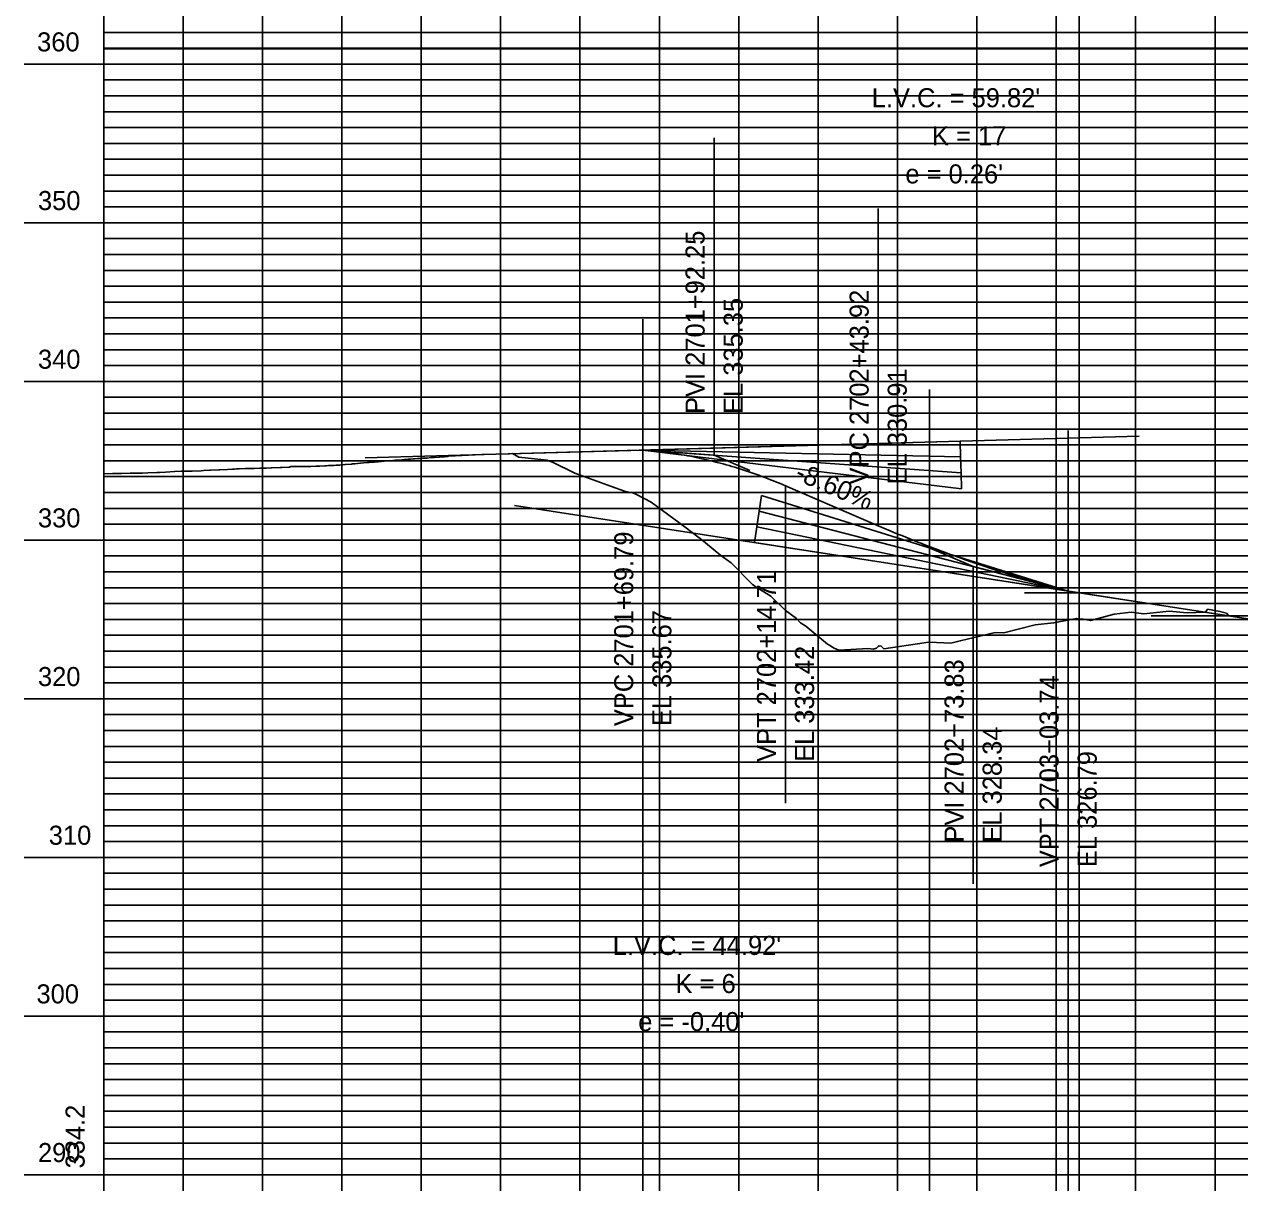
# Model space of a CAD drawing. Extents: x 1195880 to 1289360, y 2059330 to 2086925.
# Drawn here: x 1197038.8 to 1197421.6, y 2062321.8 to 2062686.8 of the extents above; entities that cross this region are included whole.
import ezdxf

# ---------------------------------------------------------------- set-up
doc = ezdxf.new("R2010")
doc.units = 0
for name, color, linetype in [('41', 7, 'Continuous'), ('Clip', 7, 'Continuous'), ('Default', 7, 'Continuous'), ('Existing Ground PGL', 7, 'Continuous'), ('Grid', 7, 'Continuous'), ('Grid Lables', 7, 'Continuous'), ('Profile', 7, 'Continuous'), ('Profile Annotation', 7, 'Continuous')]:
    doc.layers.add(name, color=color, linetype=linetype)

msp = doc.modelspace()

# ---------------------------------------------------------------- linework, layer by layer
at = {"layer": 'Clip'}
msp.add_lwpolyline([(1197063.84, 2062324.28), (1197483, 2062324.28), (1197483, 2062679.07), (1197063.84, 2062679.07)], close=True, dxfattribs=at)
at = {"layer": 'Default'}
for p, q in [((1197371.02, 2062224.28), (1197371.02, 2062868.37)), ((1197233.63, 2062274.28), (1197233.63, 2062593.89)), ((1197323.88, 2062224.28), (1197323.88, 2062571.74)), ((1197146.17, 2062550.17), (1197389.96, 2062557.06)), ((1197367.58, 2062274.28), (1197367.58, 2062558.8)), ((1197233.63, 2062552.64), (1197333.59, 2062555.47)), ((1197334.02, 2062540.47), (1197233.63, 2062552.64)), ((1197233.63, 2062552.64), (1197333.88, 2062545.47)), ((1197333.73, 2062550.47), (1197233.63, 2062552.64)), ((1197333.59, 2062555.47), (1197333.73, 2062550.47)), ((1197333.73, 2062550.47), (1197333.88, 2062545.47)), ((1197333.88, 2062545.47), (1197334.02, 2062540.47)), ((1197270.29, 2062533.39), (1197271.06, 2062538.34)), ((1197271.06, 2062538.34), (1197367.58, 2062508.21)), ((1197193.27, 2062535.2), (1197429.6, 2062498.61)), ((1197269.53, 2062528.45), (1197270.29, 2062533.39)), ((1197367.58, 2062508.21), (1197270.29, 2062533.39)), ((1197268.76, 2062523.51), (1197269.53, 2062528.45)), ((1197269.53, 2062528.45), (1197367.58, 2062508.21)), ((1197367.58, 2062508.21), (1197268.76, 2062523.51)), ((1197588.84, 2062507.68), (1197353.89, 2062507.68)), ((1197588.84, 2062500.38), (1197393.7, 2062500.38))]:
    msp.add_line(p, q, dxfattribs=at)
at = {"layer": 'Existing Ground PGL'}
msp.add_lwpolyline([(1197063.84, 2062545.18), (1197066.63, 2062545.22), (1197067.43, 2062545.24), (1197069.42, 2062545.28), (1197072.21, 2062545.33), (1197074.99, 2062545.39), (1197076.11, 2062545.42), (1197077.78, 2062545.48), (1197080.57, 2062545.59), (1197081.39, 2062545.62), (1197083.36, 2062545.73), (1197086.14, 2062545.9), (1197088.28, 2062546.05), (1197088.93, 2062546.03), (1197090.4, 2062545.99), (1197091.22, 2062545.97), (1197091.72, 2062546), (1197094.51, 2062546.13), (1197095.28, 2062546.17), (1197097.29, 2062546.27), (1197097.52, 2062546.28), (1197100.08, 2062546.41), (1197100.46, 2062546.43), (1197102.87, 2062546.56), (1197104.44, 2062546.65), (1197105.04, 2062546.68), (1197105.66, 2062546.72), (1197106.53, 2062546.77), (1197108.44, 2062546.82), (1197109.19, 2062546.84), (1197110.1, 2062546.86), (1197111.23, 2062546.89), (1197113.03, 2062546.93), (1197114.02, 2062546.96), (1197115.01, 2062546.98), (1197116.62, 2062547.02), (1197116.81, 2062547.03), (1197119.41, 2062547.12), (1197119.59, 2062547.13), (1197119.98, 2062547.14), (1197122.15, 2062547.23), (1197122.34, 2062547.29), (1197122.38, 2062547.3), (1197122.77, 2062547.42), (1197123.07, 2062547.52), (1197125.17, 2062547.51), (1197127.96, 2062547.5), (1197129.12, 2062547.49), (1197130.64, 2062547.57), (1197130.74, 2062547.57), (1197131.92, 2062547.62), (1197133.53, 2062547.7), (1197133.92, 2062547.72), (1197134.62, 2062547.74), (1197136.32, 2062547.84), (1197137.04, 2062547.88), (1197137.22, 2062547.89), (1197138.2, 2062547.94), (1197139.11, 2062548.02), (1197139.75, 2062548.07), (1197140.03, 2062548.1), (1197141.89, 2062548.26), (1197142.21, 2062548.29), (1197142.89, 2062548.35), (1197144.59, 2062548.49), (1197144.68, 2062548.5), (1197145.64, 2062548.58), (1197146.91, 2062548.69), (1197147.47, 2062548.74), (1197148.3, 2062548.81), (1197149.17, 2062548.89), (1197150.26, 2062548.99), (1197150.87, 2062549.05), (1197151.38, 2062549.1), (1197153.04, 2062549.22), (1197153.37, 2062549.24), (1197153.55, 2062549.25), (1197154.86, 2062549.36), (1197155.67, 2062549.42), (1197155.79, 2062549.43), (1197155.83, 2062549.43), (1197157.74, 2062549.59), (1197158.14, 2062549.62), (1197158.62, 2062549.66), (1197159.78, 2062549.75), (1197160.43, 2062549.79), (1197161.41, 2062549.87), (1197161.78, 2062549.9), (1197162.67, 2062549.96), (1197163.75, 2062550.03), (1197164.2, 2062550.06), (1197164.87, 2062550.1), (1197165.67, 2062550.15), (1197166.88, 2062550.26), (1197166.98, 2062550.27), (1197168.05, 2062550.35), (1197169.46, 2062550.45), (1197169.77, 2062550.47), (1197171.18, 2062550.57), (1197172.33, 2062550.66), (1197172.47, 2062550.68), (1197172.48, 2062550.68), (1197182.95, 2062551.21), (1197191.6, 2062551.45), (1197192.61, 2062551.57), (1197194.56, 2062550.38), (1197203.5, 2062549.42), (1197204.26, 2062549.17), (1197205.22, 2062548.81), (1197212.2, 2062545.38), (1197223.74, 2062541.13), (1197227.89, 2062539.74), (1197230.65, 2062539.05), (1197231.6, 2062538.69), (1197236.29, 2062536.19), (1197246.92, 2062528.33), (1197251.01, 2062525.35), (1197251.69, 2062524.75), (1197253.42, 2062523.45), (1197258.25, 2062519.43), (1197261.43, 2062517.16), (1197268.1, 2062510.38), (1197268.21, 2062510.3), (1197268.38, 2062510.16), (1197269.06, 2062509.63), (1197273.93, 2062506.58), (1197278.46, 2062502.15), (1197282, 2062499.59), (1197283.3, 2062498.21), (1197285.02, 2062497.11), (1197291.84, 2062491.52), (1197291.96, 2062491.41), (1197292.03, 2062491.35), (1197293.94, 2062490.25), (1197295.36, 2062489.6), (1197304.67, 2062490.08), (1197306.21, 2062489.96), (1197307.25, 2062490.23), (1197307.93, 2062491.01), (1197308.06, 2062490.81), (1197308.62, 2062490.97), (1197309.52, 2062490.06), (1197322.23, 2062491.86), (1197323.6, 2062492.07), (1197323.95, 2062492.12), (1197330.61, 2062491.81), (1197333.6, 2062492.51), (1197344.59, 2062495.13), (1197347.32, 2062495.01), (1197357.2, 2062497.55), (1197363.02, 2062498.2), (1197370.18, 2062499.59), (1197372.36, 2062499.39), (1197374.64, 2062498.95), (1197376.59, 2062499.48), (1197382.12, 2062500.92), (1197387.43, 2062501.53), (1197391.39, 2062501.07), (1197399.36, 2062501.86), (1197405.1, 2062501.36), (1197410.85, 2062501.52), (1197411.22, 2062502.24), (1197411.48, 2062502.51), (1197415.36, 2062501.8), (1197417.41, 2062501.26), (1197418.18, 2062500.4), (1197428.81, 2062498.76)], dxfattribs=at)
at = {"layer": 'Grid'}
for p, q in [((1197063.84, 2062224.28), (1197063.84, 2062824.28)), ((1197088.84, 2062224.28), (1197088.84, 2062824.28)), ((1197113.84, 2062224.28), (1197113.84, 2062824.28)), ((1197138.84, 2062224.28), (1197138.84, 2062824.28)), ((1197163.84, 2062224.28), (1197163.84, 2062824.28)), ((1197188.84, 2062224.28), (1197188.84, 2062824.28)), ((1197213.84, 2062224.28), (1197213.84, 2062824.28)), ((1197238.84, 2062224.28), (1197238.84, 2062824.28)), ((1197263.84, 2062224.28), (1197263.84, 2062824.28)), ((1197288.84, 2062224.28), (1197288.84, 2062824.28)), ((1197313.84, 2062224.28), (1197313.84, 2062824.28)), ((1197338.84, 2062224.28), (1197338.84, 2062824.28)), ((1197363.84, 2062224.28), (1197363.84, 2062824.28)), ((1197388.84, 2062224.28), (1197388.84, 2062824.28)), ((1197413.84, 2062224.28), (1197413.84, 2062824.28)), ((1197063.84, 2062684.28), (1197066.84, 2062684.28)), ((1197063.84, 2062684.28), (1197563.84, 2062684.28)), ((1197563.84, 2062684.28), (1197063.84, 2062684.28)), ((1197063.84, 2062679.28), (1197066.84, 2062679.28)), ((1197063.84, 2062679.28), (1197563.84, 2062679.28)), ((1197038.84, 2062674.28), (1197063.84, 2062674.28)), ((1197063.84, 2062674.28), (1197563.84, 2062674.28)), ((1197063.84, 2062669.28), (1197066.84, 2062669.28)), ((1197063.84, 2062669.28), (1197563.84, 2062669.28)), ((1197063.84, 2062664.28), (1197066.84, 2062664.28)), ((1197063.84, 2062664.28), (1197563.84, 2062664.28)), ((1197563.84, 2062664.28), (1197063.84, 2062664.28)), ((1197063.84, 2062659.28), (1197066.84, 2062659.28)), ((1197063.84, 2062659.28), (1197563.84, 2062659.28)), ((1197063.84, 2062654.28), (1197066.84, 2062654.28)), ((1197063.84, 2062654.28), (1197563.84, 2062654.28)), ((1197563.84, 2062654.28), (1197063.84, 2062654.28)), ((1197063.84, 2062649.28), (1197066.84, 2062649.28)), ((1197063.84, 2062649.28), (1197563.84, 2062649.28)), ((1197063.84, 2062644.28), (1197066.84, 2062644.28)), ((1197063.84, 2062644.28), (1197563.84, 2062644.28)), ((1197563.84, 2062644.28), (1197063.84, 2062644.28)), ((1197063.84, 2062639.28), (1197066.84, 2062639.28)), ((1197063.84, 2062639.28), (1197563.84, 2062639.28)), ((1197063.84, 2062634.28), (1197066.84, 2062634.28)), ((1197063.84, 2062634.28), (1197563.84, 2062634.28)), ((1197563.84, 2062634.28), (1197063.84, 2062634.28)), ((1197063.84, 2062629.28), (1197066.84, 2062629.28)), ((1197063.84, 2062629.28), (1197563.84, 2062629.28)), ((1197038.84, 2062624.28), (1197063.84, 2062624.28)), ((1197063.84, 2062624.28), (1197563.84, 2062624.28)), ((1197063.84, 2062619.28), (1197066.84, 2062619.28)), ((1197063.84, 2062619.28), (1197563.84, 2062619.28)), ((1197063.84, 2062614.28), (1197066.84, 2062614.28)), ((1197063.84, 2062614.28), (1197563.84, 2062614.28)), ((1197563.84, 2062614.28), (1197063.84, 2062614.28)), ((1197063.84, 2062609.28), (1197066.84, 2062609.28)), ((1197063.84, 2062609.28), (1197563.84, 2062609.28)), ((1197063.84, 2062604.28), (1197066.84, 2062604.28)), ((1197063.84, 2062604.28), (1197563.84, 2062604.28)), ((1197563.84, 2062604.28), (1197063.84, 2062604.28)), ((1197063.84, 2062599.28), (1197066.84, 2062599.28)), ((1197063.84, 2062599.28), (1197563.84, 2062599.28)), ((1197063.84, 2062594.28), (1197066.84, 2062594.28)), ((1197063.84, 2062594.28), (1197563.84, 2062594.28)), ((1197563.84, 2062594.28), (1197063.84, 2062594.28)), ((1197063.84, 2062589.28), (1197066.84, 2062589.28)), ((1197063.84, 2062589.28), (1197563.84, 2062589.28)), ((1197063.84, 2062584.28), (1197066.84, 2062584.28)), ((1197063.84, 2062584.28), (1197563.84, 2062584.28)), ((1197563.84, 2062584.28), (1197063.84, 2062584.28)), ((1197063.84, 2062579.28), (1197066.84, 2062579.28)), ((1197063.84, 2062579.28), (1197563.84, 2062579.28)), ((1197038.84, 2062574.28), (1197063.84, 2062574.28)), ((1197063.84, 2062574.28), (1197563.84, 2062574.28)), ((1197063.84, 2062569.28), (1197066.84, 2062569.28)), ((1197063.84, 2062569.28), (1197563.84, 2062569.28)), ((1197063.84, 2062564.28), (1197066.84, 2062564.28)), ((1197063.84, 2062564.28), (1197563.84, 2062564.28)), ((1197563.84, 2062564.28), (1197063.84, 2062564.28)), ((1197063.84, 2062559.28), (1197066.84, 2062559.28)), ((1197063.84, 2062559.28), (1197563.84, 2062559.28)), ((1197063.84, 2062554.28), (1197066.84, 2062554.28)), ((1197063.84, 2062554.28), (1197563.84, 2062554.28)), ((1197063.84, 2062549.28), (1197066.84, 2062549.28)), ((1197063.84, 2062549.28), (1197563.84, 2062549.28)), ((1197063.84, 2062544.28), (1197066.84, 2062544.28)), ((1197063.84, 2062544.28), (1197563.84, 2062544.28)), ((1197563.84, 2062544.28), (1197063.84, 2062544.28)), ((1197063.84, 2062539.28), (1197066.84, 2062539.28)), ((1197063.84, 2062539.28), (1197563.84, 2062539.28)), ((1197063.84, 2062534.28), (1197066.84, 2062534.28)), ((1197063.84, 2062534.28), (1197563.84, 2062534.28)), ((1197563.84, 2062534.28), (1197063.84, 2062534.28)), ((1197063.84, 2062529.28), (1197066.84, 2062529.28)), ((1197063.84, 2062529.28), (1197563.84, 2062529.28)), ((1197038.84, 2062524.28), (1197063.84, 2062524.28)), ((1197063.84, 2062524.28), (1197563.84, 2062524.28)), ((1197063.84, 2062519.28), (1197066.84, 2062519.28)), ((1197063.84, 2062519.28), (1197563.84, 2062519.28)), ((1197063.84, 2062514.28), (1197066.84, 2062514.28)), ((1197063.84, 2062514.28), (1197563.84, 2062514.28)), ((1197563.84, 2062514.28), (1197063.84, 2062514.28)), ((1197063.84, 2062509.28), (1197066.84, 2062509.28)), ((1197063.84, 2062509.28), (1197563.84, 2062509.28)), ((1197063.84, 2062504.28), (1197066.84, 2062504.28)), ((1197063.84, 2062504.28), (1197563.84, 2062504.28)), ((1197563.84, 2062504.28), (1197063.84, 2062504.28)), ((1197063.84, 2062499.28), (1197066.84, 2062499.28)), ((1197063.84, 2062499.28), (1197563.84, 2062499.28)), ((1197063.84, 2062494.28), (1197066.84, 2062494.28)), ((1197063.84, 2062494.28), (1197563.84, 2062494.28)), ((1197563.84, 2062494.28), (1197063.84, 2062494.28)), ((1197063.84, 2062489.28), (1197066.84, 2062489.28)), ((1197063.84, 2062489.28), (1197563.84, 2062489.28)), ((1197063.84, 2062484.28), (1197066.84, 2062484.28)), ((1197063.84, 2062484.28), (1197563.84, 2062484.28)), ((1197563.84, 2062484.28), (1197063.84, 2062484.28)), ((1197063.84, 2062479.28), (1197066.84, 2062479.28)), ((1197063.84, 2062479.28), (1197563.84, 2062479.28)), ((1197038.84, 2062474.28), (1197063.84, 2062474.28)), ((1197063.84, 2062474.28), (1197563.84, 2062474.28)), ((1197063.84, 2062469.28), (1197066.84, 2062469.28)), ((1197063.84, 2062469.28), (1197563.84, 2062469.28)), ((1197063.84, 2062464.28), (1197066.84, 2062464.28)), ((1197063.84, 2062464.28), (1197563.84, 2062464.28)), ((1197563.84, 2062464.28), (1197063.84, 2062464.28)), ((1197063.84, 2062459.28), (1197066.84, 2062459.28)), ((1197063.84, 2062459.28), (1197563.84, 2062459.28)), ((1197063.84, 2062454.28), (1197066.84, 2062454.28)), ((1197063.84, 2062454.28), (1197563.84, 2062454.28)), ((1197063.84, 2062449.28), (1197066.84, 2062449.28)), ((1197063.84, 2062449.28), (1197563.84, 2062449.28)), ((1197063.84, 2062444.28), (1197066.84, 2062444.28)), ((1197063.84, 2062444.28), (1197563.84, 2062444.28)), ((1197563.84, 2062444.28), (1197063.84, 2062444.28)), ((1197063.84, 2062439.28), (1197066.84, 2062439.28)), ((1197063.84, 2062439.28), (1197563.84, 2062439.28)), ((1197063.84, 2062434.28), (1197066.84, 2062434.28)), ((1197063.84, 2062434.28), (1197563.84, 2062434.28)), ((1197563.84, 2062434.28), (1197063.84, 2062434.28)), ((1197063.84, 2062429.28), (1197066.84, 2062429.28)), ((1197063.84, 2062429.28), (1197563.84, 2062429.28)), ((1197038.84, 2062424.28), (1197063.84, 2062424.28)), ((1197063.84, 2062424.28), (1197563.84, 2062424.28)), ((1197063.84, 2062419.28), (1197066.84, 2062419.28)), ((1197063.84, 2062419.28), (1197563.84, 2062419.28)), ((1197063.84, 2062414.28), (1197066.84, 2062414.28)), ((1197063.84, 2062414.28), (1197563.84, 2062414.28)), ((1197563.84, 2062414.28), (1197063.84, 2062414.28)), ((1197063.84, 2062409.28), (1197066.84, 2062409.28)), ((1197063.84, 2062409.28), (1197563.84, 2062409.28)), ((1197063.84, 2062404.28), (1197066.84, 2062404.28)), ((1197063.84, 2062404.28), (1197563.84, 2062404.28)), ((1197563.84, 2062404.28), (1197063.84, 2062404.28)), ((1197063.84, 2062399.28), (1197066.84, 2062399.28)), ((1197063.84, 2062399.28), (1197563.84, 2062399.28)), ((1197063.84, 2062394.28), (1197066.84, 2062394.28)), ((1197063.84, 2062394.28), (1197563.84, 2062394.28)), ((1197563.84, 2062394.28), (1197063.84, 2062394.28)), ((1197063.84, 2062389.28), (1197066.84, 2062389.28)), ((1197063.84, 2062389.28), (1197563.84, 2062389.28)), ((1197063.84, 2062384.28), (1197066.84, 2062384.28)), ((1197063.84, 2062384.28), (1197563.84, 2062384.28)), ((1197563.84, 2062384.28), (1197063.84, 2062384.28)), ((1197063.84, 2062379.28), (1197066.84, 2062379.28)), ((1197063.84, 2062379.28), (1197563.84, 2062379.28)), ((1197038.84, 2062374.28), (1197063.84, 2062374.28)), ((1197063.84, 2062374.28), (1197563.84, 2062374.28)), ((1197063.84, 2062369.28), (1197066.84, 2062369.28)), ((1197063.84, 2062369.28), (1197563.84, 2062369.28)), ((1197063.84, 2062364.28), (1197066.84, 2062364.28)), ((1197063.84, 2062364.28), (1197563.84, 2062364.28)), ((1197563.84, 2062364.28), (1197063.84, 2062364.28)), ((1197063.84, 2062359.28), (1197066.84, 2062359.28)), ((1197063.84, 2062359.28), (1197563.84, 2062359.28)), ((1197063.84, 2062354.28), (1197066.84, 2062354.28)), ((1197063.84, 2062354.28), (1197563.84, 2062354.28)), ((1197563.84, 2062354.28), (1197063.84, 2062354.28)), ((1197063.84, 2062349.28), (1197066.84, 2062349.28)), ((1197563.84, 2062349.28), (1197063.84, 2062349.28)), ((1197063.84, 2062344.28), (1197066.84, 2062344.28)), ((1197063.84, 2062344.28), (1197563.84, 2062344.28)), ((1197563.84, 2062344.28), (1197063.84, 2062344.28)), ((1197063.84, 2062339.28), (1197066.84, 2062339.28)), ((1197063.84, 2062339.28), (1197563.84, 2062339.28)), ((1197063.84, 2062334.28), (1197066.84, 2062334.28)), ((1197063.84, 2062334.28), (1197563.84, 2062334.28)), ((1197563.84, 2062334.28), (1197063.84, 2062334.28)), ((1197063.84, 2062329.28), (1197066.84, 2062329.28)), ((1197063.84, 2062329.28), (1197563.84, 2062329.28)), ((1197038.84, 2062324.28), (1197063.84, 2062324.28)), ((1197063.84, 2062324.28), (1197563.84, 2062324.28))]:
    msp.add_line(p, q, dxfattribs=at)
at = {"layer": 'Profile'}
for p, q in [((1197191.53, 2062551.45), (1197233.63, 2062552.64)), ((1197233.63, 2062552.64), (1197233.64, 2062552.64)), ((1197278.56, 2062541.38), (1197307.76, 2062528.82)), ((1197367.58, 2062508.21), (1197367.58, 2062508.21)), ((1197367.58, 2062508.21), (1197418.17, 2062500.38))]:
    msp.add_line(p, q, dxfattribs=at)
for points in [[(1197233.64, 2062552.64), (1197234.57, 2062552.57), (1197235.51, 2062552.49), (1197236.44, 2062552.41), (1197237.38, 2062552.32), (1197238.32, 2062552.22), (1197239.25, 2062552.11), (1197240.19, 2062552), (1197241.12, 2062551.88), (1197242.06, 2062551.76), (1197242.99, 2062551.62), (1197243.93, 2062551.48), (1197244.87, 2062551.33), (1197245.8, 2062551.18), (1197246.74, 2062551.02), (1197247.67, 2062550.85), (1197248.61, 2062550.68), (1197249.55, 2062550.49), (1197250.48, 2062550.3), (1197251.42, 2062550.11), (1197252.35, 2062549.9), (1197253.29, 2062549.69), (1197254.22, 2062549.48), (1197255.16, 2062549.25), (1197257.03, 2062548.78), (1197257.97, 2062548.54), (1197258.9, 2062548.29), (1197259.84, 2062548.03), (1197260.78, 2062547.76), (1197261.71, 2062547.49), (1197262.65, 2062547.21), (1197263.58, 2062546.92), (1197264.52, 2062546.63), (1197265.45, 2062546.33), (1197266.39, 2062546.02), (1197267.33, 2062545.7), (1197268.26, 2062545.38), (1197269.2, 2062545.05), (1197270.13, 2062544.71), (1197271.07, 2062544.37), (1197272.01, 2062544.02), (1197272.94, 2062543.66), (1197273.88, 2062543.3), (1197274.81, 2062542.93), (1197275.75, 2062542.55), (1197276.68, 2062542.17), (1197277.62, 2062541.77), (1197278.56, 2062541.38)], [(1197307.76, 2062528.82), (1197309.01, 2062528.28), (1197310.25, 2062527.75), (1197311.5, 2062527.23), (1197312.74, 2062526.71), (1197313.99, 2062526.19), (1197315.24, 2062525.68), (1197316.48, 2062525.17), (1197317.73, 2062524.67), (1197318.98, 2062524.17), (1197320.22, 2062523.68), (1197321.47, 2062523.19), (1197322.71, 2062522.7), (1197323.96, 2062522.22), (1197325.21, 2062521.75), (1197326.45, 2062521.28), (1197327.7, 2062520.81), (1197328.95, 2062520.35), (1197330.19, 2062519.89), (1197331.44, 2062519.44), (1197332.68, 2062518.99), (1197333.93, 2062518.54), (1197335.18, 2062518.1), (1197336.42, 2062517.67), (1197338.92, 2062516.81), (1197340.16, 2062516.38), (1197341.41, 2062515.97), (1197342.65, 2062515.55), (1197343.9, 2062515.14), (1197345.15, 2062514.74), (1197346.39, 2062514.34), (1197347.64, 2062513.94), (1197348.89, 2062513.55), (1197350.13, 2062513.16), (1197351.38, 2062512.78), (1197352.62, 2062512.4), (1197353.87, 2062512.03), (1197355.12, 2062511.66), (1197356.36, 2062511.29), (1197357.61, 2062510.93), (1197358.86, 2062510.58), (1197360.1, 2062510.23), (1197361.35, 2062509.88), (1197362.59, 2062509.54), (1197363.84, 2062509.2), (1197365.09, 2062508.87), (1197366.33, 2062508.54), (1197367.58, 2062508.21)]]:
    msp.add_lwpolyline(points, dxfattribs=at)
at = {"layer": 'Profile Annotation'}
for p, q in [((1197256.1, 2062551.03), (1197256.1, 2062651.03)), ((1197307.76, 2062528.82), (1197307.76, 2062628.82)), ((1197233.63, 2062452.64), (1197233.63, 2062552.64)), ((1197244.87, 2062551.84), (1197256.1, 2062551.03)), ((1197256.1, 2062551.03), (1197267.33, 2062546.21)), ((1197278.56, 2062541.38), (1197278.56, 2062441.38)), ((1197322.71, 2062522.38), (1197337.67, 2062515.95)), ((1197337.67, 2062515.95), (1197352.62, 2062512.08)), ((1197337.67, 2062515.95), (1197337.67, 2062415.95)), ((1197367.58, 2062408.21), (1197367.58, 2062508.21))]:
    msp.add_line(p, q, dxfattribs=at)

# ---------------------------------------------------------------- texts
at = {"layer": '41'}
msp.add_text('334.2', height=6, rotation=90, dxfattribs=at).set_placement((1197057.84, 2062326.28))
at = {"layer": 'Grid Lables'}
for s, p in [('360', (1197042.87, 2062678.28)), ('350', (1197043.15, 2062628.28)), ('340', (1197043.15, 2062578.28)), ('330', (1197043.15, 2062528.28)), ('320', (1197043.15, 2062478.28)), ('310', (1197046.55, 2062428.28)), ('300', (1197042.68, 2062378.28)), ('290', (1197043.15, 2062328.28))]:
    msp.add_text(s, height=6, rotation=360, dxfattribs=at).set_placement(p)
at = {"layer": 'Profile Annotation'}
for s, p in [("L.V.C. = 59.82'", (1197305.73, 2062660.68)), ('K = 17', (1197324.68, 2062648.68)), ("e = 0.26'", (1197316.32, 2062636.68)), ("L.V.C. = 44.92'", (1197224.16, 2062393.55)), ('K = 6', (1197243.93, 2062381.55)), ("e = -0.40'", (1197232.19, 2062369.55))]:
    msp.add_text(s, height=6, dxfattribs=at).set_placement(p)
for s, rotation, p in [('PVI 2701+92.25', 90, (1197253.1, 2062564.03)), ('VPC 2702+43.92', 90, (1197304.76, 2062541.82)), ('EL 335.35', 90, (1197265.1, 2062564.03)), ('EL 330.91', 90, (1197316.76, 2062541.82)), ('-8.60%', 336.7296, (1197281.17, 2062543.52)), ('VPC 2701+69.79', 90, (1197230.63, 2062465.64)), ('VPT 2702+14.71', 90, (1197275.56, 2062454.38)), ('EL 335.67', 90, (1197242.63, 2062465.64)), ('EL 333.42', 90, (1197287.56, 2062454.38)), ('PVI 2702+73.83', 90, (1197334.67, 2062428.95)), ('VPT 2703+03.74', 90, (1197364.58, 2062421.21)), ('EL 328.34', 90, (1197346.67, 2062428.95)), ('EL 326.79', 90, (1197376.58, 2062421.21))]:
    msp.add_text(s, height=6, rotation=rotation, dxfattribs=at).set_placement(p)

doc.saveas('drawing.dxf')
